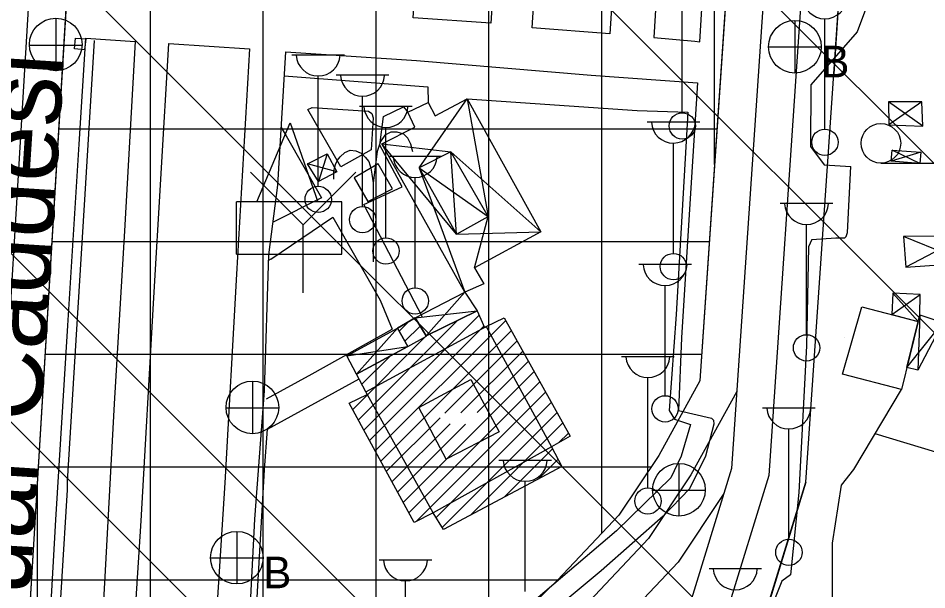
# Model space of a CAD drawing. Extents: x 417995 to 421451, y 4454518 to 4458015.
# Drawn here: x 420623.1 to 420743.9, y 4456059.6 to 4456135.7 of the extents above; entities that cross this region are included whole.
import ezdxf

# ---------------------------------------------------------------- set-up
doc = ezdxf.new("R2010")
doc.units = 0
for name, color, linetype in [('ADAKENARI', 7, 'Continuous'), ('B_Dini tesis', 7, 'Continuous'), ('B_Mesken', 7, 'Continuous'), ('B_Sundurma', 7, 'Continuous'), ('B_Tarama', 7, 'Continuous'), ('B_Teras', 7, 'Continuous'), ('Hid_Havuz', 7, 'Continuous'), ('KALDIRIM_FAT', 7, 'Continuous'), ('PL_SAY_SPOR', 7, 'Continuous'), ('PL_TİCARET', 7, 'Continuous'), ('S_Abide', 7, 'Continuous'), ('S_Cad_Sok_Lambasi', 7, 'Continuous'), ('S_Rogar_Kapagi', 7, 'Continuous'), ('S_Rogar_Kapagi_Buski', 7, 'Continuous'), ('S_Tek_Agac', 7, 'Continuous'), ('S_Yangin_Vanasi', 7, 'Continuous'), ('Sinir_Cit_bir_taraf', 7, 'Continuous'), ('Sinir_itirazli_Mulkiyet', 7, 'Continuous'), ('Sinir_Parmaklik_bir_taraf', 7, 'Continuous'), ('Sinir_Yesil_Cit', 7, 'Continuous'), ('SN_TR_SIVILASMA', 7, 'Continuous'), ('TRFAT_SPOR', 7, 'Continuous'), ('TRFAT_TİCARET', 7, 'Continuous'), ('Y_Cadde_Yol', 7, 'Continuous'), ('Yol_Kaldirim_kenari_bordurtasi', 7, 'Continuous'), ('Yol_Sose', 7, 'Continuous')]:
    doc.layers.add(name, color=color, linetype=linetype)

msp = doc.modelspace()

# ---------------------------------------------------------------- linework, layer by layer
at = {"layer": 'ADAKENARI'}
for p, q in [((420742.27, 4456506.47), (420713.73, 4456087.47)), ((420748.52, 4456377.44), (420731.55, 4456128.29)), ((420623.45, 4456037.14), (420640, 4456310.1)), ((420727.85, 4456073.98), (420731.55, 4456128.29)), ((420713.73, 4456087.47), (420708.28, 4456077.52)), ((420708.28, 4456077.52), (420702.99, 4456069.58)), ((420727.85, 4456073.98), (420714.2, 4456029.58)), ((420702.99, 4456069.58), (420694.8, 4456060.91)), ((420694.8, 4456060.91), (420687.13, 4456053.49))]:
    msp.add_line(p, q, dxfattribs=at)
at = {"layer": 'B_Dini tesis'}
for points in [[(420677.36, 4456093.42), (420684.13, 4456096.75), (420685.1, 4456094.55), (420685.31, 4456094.67), (420687.74, 4456095.84), (420696.52, 4456080.08), (420694.01, 4456078.66), (420695.37, 4456076.05), (420679.64, 4456067.68), (420678.29, 4456069.87), (420675.75, 4456068.6), (420667.1, 4456084.46), (420669.53, 4456085.64), (420669.35, 4456085.97), (420668.1, 4456088.36), (420674.92, 4456092.02), (420673.54, 4456094.45), (420675.88, 4456095.82)], [(420685.31, 4456094.67), (420694.01, 4456078.66), (420678.29, 4456069.87), (420669.35, 4456085.97)], [(420676.36, 4456083.9), (420683.29, 4456087.65), (420687.04, 4456080.67), (420680.03, 4456077.02)]]:
    msp.add_lwpolyline(points, close=True, dxfattribs=at)
at = {"layer": 'B_Mesken'}
msp.add_lwpolyline([(420735.26, 4456097.32), (420742.75, 4456095.37), (420740.57, 4456086.29), (420732.71, 4456088.36)], close=True, dxfattribs=at)
at = {"layer": 'B_Sundurma'}
for p, q in [((420676.44, 4456115.8), (420682.81, 4456125)), ((420682.81, 4456125), (420685.61, 4456109.31)), ((420743.37, 4456121.35), (420738.82, 4456124.6)), ((420743.28, 4456124.6), (420738.86, 4456121.5)), ((420681.38, 4456106.99), (420671.44, 4456119.01)), ((420671.44, 4456119.01), (420680.64, 4456117.93)), ((420664.17, 4456117.66), (420663.05, 4456113.97)), ((420680.64, 4456117.93), (420692.59, 4456107.3)), ((420681.38, 4456106.99), (420680.64, 4456117.93)), ((420743.12, 4456117.87), (420739.18, 4456116.67)), ((420743, 4456116.38), (420739.33, 4456118.15)), ((420665.46, 4456115.27), (420661.59, 4456116.31)), ((420676.44, 4456115.8), (420682.5, 4456099.25)), ((420676.44, 4456115.8), (420685.61, 4456109.31)), ((420683.79, 4456102.49), (420685.61, 4456109.31)), ((420681.38, 4456106.99), (420692.59, 4456107.3)), ((420749.31, 4456103.17), (420740.84, 4456106.65)), ((420749.05, 4456106.74), (420741.13, 4456102.58)), ((420682.5, 4456099.25), (420677.36, 4456093.42)), ((420739.27, 4456096.28), (420743.03, 4456098.96)), ((420742.75, 4456095.37), (420739.39, 4456099.13)), ((420675.88, 4456095.82), (420684.13, 4456096.75)), ((420743.01, 4456096.25), (420742.74, 4456088.87)), ((420741.27, 4456089.22), (420746.07, 4456095.23)), ((420668.1, 4456088.36), (420673.54, 4456094.45)), ((420666.8, 4456090.8), (420674.92, 4456092.02))]:
    msp.add_line(p, q, dxfattribs=at)
for points in [[(420630.71, 4456133.04), (420632.09, 4456132.95), (420631.93, 4456131.5), (420630.58, 4456131.61)], [(420682.5, 4456099.25), (420671.44, 4456119.01), (420675.84, 4456121.21), (420674.92, 4456123.22), (420677.63, 4456124.47), (420678.57, 4456122.72), (420682.81, 4456125), (420692.59, 4456107.3), (420683.79, 4456102.49), (420685.03, 4456100.34), (420682.5, 4456099.25)], [(420743.37, 4456121.35), (420743.28, 4456124.6), (420738.82, 4456124.6), (420738.86, 4456121.5)], [(420664.17, 4456117.66), (420665.46, 4456115.27), (420663.05, 4456113.97), (420661.59, 4456116.31)], [(420681.38, 4456106.99), (420685.61, 4456109.31), (420680.64, 4456117.93), (420676.44, 4456115.8)], [(420743.12, 4456117.87), (420743, 4456116.38), (420739.18, 4456116.67), (420739.33, 4456118.15)], [(420749.31, 4456103.17), (420749.05, 4456106.74), (420740.84, 4456106.65), (420741.13, 4456102.58)], [(420675.88, 4456095.82), (420682.5, 4456099.25), (420684.13, 4456096.75), (420677.36, 4456093.42)], [(420739.27, 4456096.28), (420742.75, 4456095.37), (420743.01, 4456096.25), (420743.03, 4456098.96), (420739.39, 4456099.13)], [(420741.27, 4456089.22), (420742.75, 4456095.37), (420743.01, 4456096.25), (420746.07, 4456095.23), (420742.74, 4456088.87)], [(420668.1, 4456088.36), (420666.8, 4456090.8), (420673.54, 4456094.45), (420674.92, 4456092.02)]]:
    msp.add_lwpolyline(points, close=True, dxfattribs=at)
at = {"layer": 'B_Tarama'}
for p, q in [((420669.06, 4456080.87), (420684.38, 4456096.19)), ((420668.31, 4456082.24), (420681.54, 4456095.47)), ((420669.81, 4456079.5), (420685.03, 4456094.72)), ((420670.56, 4456078.13), (420687.93, 4456095.5)), ((420673.76, 4456094.06), (420675.02, 4456095.32)), ((420674.53, 4456092.71), (420676.55, 4456094.73)), ((420667.56, 4456083.61), (420677.36, 4456093.42)), ((420671.31, 4456076.75), (420688.69, 4456094.13)), ((420679.85, 4456083.17), (420689.45, 4456092.77)), ((420681.98, 4456083.19), (420690.2, 4456091.41)), ((420668.81, 4456086.99), (420672.6, 4456090.78)), ((420684.14, 4456083.23), (420690.96, 4456090.05)), ((420674.3, 4456071.26), (420691.72, 4456088.68)), ((420675.05, 4456069.89), (420692.48, 4456087.32)), ((420676.02, 4456068.74), (420693.24, 4456085.96)), ((420678.67, 4456069.26), (420694, 4456084.6)), ((420672.05, 4456075.38), (420679.22, 4456082.55)), ((420679.47, 4456067.95), (420694.76, 4456083.23)), ((420672.8, 4456074.01), (420680.53, 4456081.73)), ((420673.55, 4456072.64), (420682.59, 4456081.68)), ((420683.24, 4456069.59), (420695.52, 4456081.87)), ((420694.97, 4456079.2), (420696.28, 4456080.51)), ((420687.77, 4456072.01), (420694.15, 4456078.39)), ((420692.31, 4456074.42), (420694.88, 4456076.99))]:
    msp.add_line(p, q, dxfattribs=at)
at = {"layer": 'B_Teras'}
msp.add_lwpolyline([(420673.54, 4456094.45), (420674.92, 4456092.02), (420677.38, 4456093.39), (420675.88, 4456095.82)], close=True, dxfattribs=at)
at = {"layer": 'Hid_Havuz'}
for points in [[(420675.56, 4456117.91), (420675.31, 4456118.96), (420674.93, 4456119.73), (420674.37, 4456120.29), (420673.49, 4456120.54), (420672.65, 4456120.54), (420671.85, 4456120.15), (420671.29, 4456119.31), (420670.83, 4456117.98), (420670.31, 4456113.78)], [(420665.06, 4456114.27), (420665.09, 4456115.29), (420665.3, 4456116.23), (420665.58, 4456116.83), (420665.9, 4456117.28), (420666.56, 4456117.84), (420667.26, 4456118.16), (420668, 4456118.05), (420668.7, 4456117.74), (420669.26, 4456117.21), (420669.71, 4456116.65), (420669.99, 4456115.74), (420670.13, 4456114.94), (420670.31, 4456113.78), (420670.31, 4456103.28)]]:
    msp.add_lwpolyline(points, dxfattribs=at)
msp.add_lwpolyline([(420667.8, 4456114.48), (420669.58, 4456111.3), (420672.89, 4456113.02), (420670.97, 4456116.33)], close=True, dxfattribs=at)
at = {"layer": 'KALDIRIM_FAT'}
for p, q in [((420747.16, 4456504.72), (420717.95, 4456075.79)), ((420752.15, 4456504.38), (420722.9, 4456074.87)), ((420618.56, 4456039.04), (420635.14, 4456312.53)), ((420718.64, 4456086.03), (420712.56, 4456074.93)), ((420717.95, 4456075.79), (420701.55, 4456022.47)), ((420722.9, 4456074.87), (420706.68, 4456022.13)), ((420712.56, 4456074.93), (420706.92, 4456066.45)), ((420716.84, 4456072.34), (420710.84, 4456063.33)), ((420716.94, 4456072.51), (420716.84, 4456072.34)), ((420706.92, 4456066.45), (420698.36, 4456057.39)), ((420710.84, 4456063.33), (420701.91, 4456053.88))]:
    msp.add_line(p, q, dxfattribs=at)
at = {"layer": 'PL_SAY_SPOR'}
msp.add_lwpolyline([(420858.4, 4456215.86), (420846.76, 4456021.02), (420843.59, 4456018.22), (420716.31, 4456026.52), (420714.2, 4456029.58), (420727.85, 4456073.98), (420731.55, 4456128.29), (420748.52, 4456377.44), (420853.02, 4456372.3), (420866.39, 4456349.6)], close=True, dxfattribs=at)
at = {"layer": 'PL_TİCARET'}
msp.add_lwpolyline([(420742.27, 4456506.47), (420713.73, 4456087.47), (420708.28, 4456077.52), (420702.99, 4456069.58), (420694.8, 4456060.91), (420687.13, 4456053.49), (420677.56, 4456046.59), (420663.97, 4456038.32), (420651.15, 4456031.6), (420647.64, 4456030.99), (420629.4, 4456032.18), (420626.42, 4456033.36), (420623.45, 4456037.14), (420640, 4456310.1)], dxfattribs=at)
at = {"layer": 'S_Abide'}
for p, q in [((420654.84, 4456111.29), (420659.29, 4456121.79)), ((420659.29, 4456121.79), (420662.96, 4456111.29)), ((420652.15, 4456104.29), (420652.15, 4456111.29)), ((420666.15, 4456111.29), (420652.15, 4456111.29)), ((420666.15, 4456104.29), (420666.15, 4456111.29)), ((420666.15, 4456104.29), (420666.15, 4456111.05)), ((420652.15, 4456104.29), (420666.15, 4456104.29))]:
    msp.add_line(p, q, dxfattribs=at)
at = {"layer": 'S_Cad_Sok_Lambasi'}
for p, q in [((420711.41, 4456123.12), (420711.41, 4456137.8)), ((420730.37, 4456120.95), (420730.37, 4456135.63)), ((420659.5, 4456130.85), (420666.5, 4456130.85)), ((420663, 4456113.35), (420663, 4456128.02)), ((420665.4, 4456128.15), (420672.4, 4456128.15)), ((420668.9, 4456110.65), (420668.9, 4456125.32)), ((420668.51, 4456123.99), (420675.51, 4456123.99)), ((420672.01, 4456106.49), (420672.01, 4456121.16)), ((420706.72, 4456121.91), (420713.72, 4456121.91)), ((420710.22, 4456104.41), (420710.22, 4456119.09)), ((420672.4, 4456117.34), (420679.4, 4456117.34)), ((420675.9, 4456099.84), (420675.9, 4456114.51)), ((420724.43, 4456111.09), (420731.43, 4456111.09)), ((420727.93, 4456093.59), (420727.93, 4456108.27)), ((420705.62, 4456102.97), (420712.62, 4456102.97)), ((420709.12, 4456085.47), (420709.12, 4456100.14)), ((420703.34, 4456090.71), (420710.34, 4456090.71)), ((420706.84, 4456073.21), (420706.84, 4456087.88)), ((420722.08, 4456083.88), (420729.08, 4456083.88)), ((420725.58, 4456066.38), (420725.58, 4456081.05)), ((420687.02, 4456076.9), (420694.02, 4456076.9)), ((420690.52, 4456059.4), (420690.52, 4456074.08)), ((420671.09, 4456063.65), (420678.09, 4456063.65)), ((420714.96, 4456062.46), (420721.96, 4456062.46)), ((420674.59, 4456046.15), (420674.59, 4456060.82))]:
    msp.add_line(p, q, dxfattribs=at)
for centre in [(420711.41, 4456121.37), (420730.37, 4456119.2), (420663, 4456111.6), (420668.9, 4456108.9), (420672.01, 4456104.74), (420710.22, 4456102.66), (420675.9, 4456098.09), (420727.93, 4456091.84), (420709.12, 4456083.72), (420706.84, 4456071.46), (420725.58, 4456064.63)]:
    msp.add_circle(centre, 1.75, dxfattribs=at)
for centre in [(420730.37, 4456138.56), (420663, 4456130.95), (420668.9, 4456128.25), (420672.01, 4456124.09), (420710.22, 4456122.02), (420675.9, 4456117.44), (420727.93, 4456111.19), (420709.12, 4456103.07), (420706.84, 4456090.81), (420725.58, 4456083.98), (420690.52, 4456077.01), (420674.59, 4456063.75), (420718.46, 4456062.57)]:
    msp.add_arc(centre, 2.93, 183.298, 356.9072, dxfattribs=at)
at = {"layer": 'S_Rogar_Kapagi'}
for p, q in [((420628.15, 4456128.68), (420628.15, 4456135.68)), ((420624.58, 4456132.14), (420631.58, 4456132.14)), ((420654.3, 4456080.39), (420654.3, 4456087.39)), ((420650.73, 4456083.86), (420657.73, 4456083.86)), ((420711.01, 4456069.43), (420711.01, 4456076.43)), ((420707.44, 4456072.89), (420714.44, 4456072.89))]:
    msp.add_line(p, q, dxfattribs=at)
for centre in [(420628.1, 4456132.21), (420654.25, 4456083.92), (420710.96, 4456072.96)]:
    msp.add_circle(centre, 3.5, dxfattribs=at)
at = {"layer": 'S_Rogar_Kapagi_Buski'}
for p, q in [((420726.38, 4456135.41), (420726.38, 4456128.41)), ((420722.88, 4456131.91), (420729.88, 4456131.91)), ((420652.18, 4456067.42), (420652.18, 4456060.42)), ((420648.68, 4456063.92), (420655.68, 4456063.92))]:
    msp.add_line(p, q, dxfattribs=at)
for centre in [(420726.38, 4456131.91), (420652.18, 4456063.92)]:
    msp.add_circle(centre, 3.5, dxfattribs=at)
at = {"layer": 'S_Tek_Agac'}
msp.add_line((420737.82, 4456116.43), (420744.82, 4456116.43), dxfattribs=at)
msp.add_circle((420737.82, 4456119.06), 2.63, dxfattribs=at)
at = {"layer": 'S_Yangin_Vanasi'}
for p, q in [((420660.98, 4456108.22), (420653.98, 4456115.22)), ((420660.98, 4456108.22), (420668.01, 4456115.22)), ((420660.98, 4456099.16), (420660.98, 4456108.22))]:
    msp.add_line(p, q, dxfattribs=at)
at = {"layer": 'Sinir_Cit_bir_taraf'}
for points in [[(420732.57, 4456073.56), (420734.2, 4456075.64), (420740.57, 4456086.29)], [(420729.4, 4456033.55), (420730.14, 4456036.39), (420731.4, 4456052.42), (420731.39, 4456065.86), (420732.57, 4456073.56)]]:
    msp.add_lwpolyline(points, dxfattribs=at)
at = {"layer": 'Sinir_itirazli_Mulkiyet'}
msp.add_lwpolyline([(420783.51, 4456067.02), (420774.06, 4456070.08), (420745.11, 4456077.97), (420737.04, 4456080.39)], dxfattribs=at)
at = {"layer": 'Sinir_Parmaklik_bir_taraf'}
msp.add_lwpolyline([(420633.19, 4456132.75), (420631.96, 4456112.28), (420630.53, 4456089.25), (420629.61, 4456074.04), (420629.6, 4456072.95), (420628.12, 4456048.47), (420627.59, 4456039.75)], dxfattribs=at)
at = {"layer": 'Sinir_Yesil_Cit'}
for points in [[(420682.81, 4456125), (420705.39, 4456123.43), (420712.13, 4456123.21)], [(420712.13, 4456123.21), (420710.61, 4456096.28), (420709.66, 4456083.51), (420710.39, 4456082.33), (420712.48, 4456081.66), (420711.25, 4456077.44), (420709.88, 4456074.53), (420702.64, 4456067.48), (420682.72, 4456050.5), (420668.55, 4456037.71), (420662.7, 4456032.94), (420657.34, 4456030.13), (420653.36, 4456029.27), (420653.72, 4456038.55), (420655.86, 4456075.62), (420656.27, 4456081.02), (420668.43, 4456087.74)], [(420656.12, 4456085.07), (420662.19, 4456088.4), (420672.84, 4456094.34)]]:
    msp.add_lwpolyline(points, dxfattribs=at)
at = {"layer": 'SN_TR_SIVILASMA'}
for p, q in [((421272.55, 4455588.71), (420264.03, 4456597.24)), ((421272.32, 4455566.5), (420257.91, 4456580.91)), ((421271.63, 4455499.84), (420239.54, 4456531.93)), ((421271.16, 4455455.4), (420227.3, 4456499.27)), ((421270.93, 4455433.18), (420221.05, 4456483.06))]:
    msp.add_line(p, q, dxfattribs=at)
at = {"layer": 'TRFAT_SPOR'}
for p, q in [((420732.95, 4456130.72), (420732.95, 4456130.72)), ((420732.95, 4456111.97), (420732.95, 4456111.97)), ((420732.95, 4456093.22), (420732.95, 4456093.22)), ((420732.95, 4456074.47), (420732.95, 4456074.47))]:
    msp.add_line(p, q, dxfattribs=at)
at = {"layer": 'TRFAT_TİCARET'}
for p, q in [((420640.69, 4456031.44), (420640.69, 4456593)), ((420655.69, 4456033.98), (420655.69, 4456580.72)), ((420700.69, 4456067.15), (420700.69, 4456543.85)), ((420715.69, 4456116.24), (420715.69, 4456531.57)), ((420670.69, 4456042.41), (420670.69, 4456309.64)), ((420685.69, 4456052.45), (420685.69, 4456309.64)), ((420628.53, 4456120.99), (420716.01, 4456120.99)), ((420627.62, 4456105.99), (420714.99, 4456105.99)), ((420626.72, 4456090.99), (420713.97, 4456090.99)), ((420625.81, 4456075.99), (420707.26, 4456075.99)), ((420625.69, 4456034.29), (420625.69, 4456074.08)), ((420624.9, 4456060.99), (420694.88, 4456060.99))]:
    msp.add_line(p, q, dxfattribs=at)
at = {"layer": 'Yol_Kaldirim_kenari_bordurtasi'}
for points in [[(420658.49, 4456128.02), (420677.56, 4456126.57), (420677.63, 4456124.47)], [(420666, 4456115.94), (420661.6, 4456123.57), (420662.18, 4456123.84), (420669.69, 4456123.32), (420670.15, 4456123.03), (420670.29, 4456122.44), (420670.03, 4456118.18), (420666, 4456115.94)], [(420676.85, 4456095.93), (420669.07, 4456110.92), (420674.15, 4456113.28), (420671.19, 4456118.8), (420671.7, 4456122.64), (420674.33, 4456123.9), (420674.92, 4456123.22)], [(420658.08, 4456121.18), (420658.76, 4456120.07), (420663.43, 4456111.81), (420656.99, 4456108.58)], [(420656.72, 4456103.65), (420664.96, 4456109.24), (420671.22, 4456098.18), (420672.84, 4456094.34)], [(420656.72, 4456103.65), (420656.41, 4456103.46)]]:
    msp.add_lwpolyline(points, dxfattribs=at)
at = {"layer": 'Yol_Sose'}
for points in [[(420739.88, 4456293.42), (420742.03, 4456290.05), (420743.84, 4456286.82), (420745.4, 4456285.19), (420751.19, 4456284.32), (420753.96, 4456282.84), (420754.46, 4456281.25), (420754.36, 4456263.79), (420753.49, 4456240.81), (420752.09, 4456211.91), (420750.59, 4456188.83), (420747.12, 4456156.46), (420743.84, 4456137.51), (420735.92, 4456137.21), (420734.68, 4456133.91)], [(420675.61, 4456135.77), (420683.19, 4456251.24), (420686.42, 4456251.07), (420686.51, 4456253.39), (420690.2, 4456253.13), (420690.1, 4456250.9), (420693.34, 4456250.83), (420685.94, 4456135.04), (420675.61, 4456135.77)], [(420691.43, 4456134.42), (420698.93, 4456250.28), (420701.65, 4456250.09), (420701.93, 4456252.53), (420706.23, 4456252.21), (420706.15, 4456249.63), (420709.2, 4456249.54), (420701.79, 4456133.61), (420691.43, 4456134.42)], [(420721.51, 4456251.12), (420714.8, 4456251.47), (420707.63, 4456133.16), (420713.06, 4456132.65)], [(420713.06, 4456132.65), (420713.73, 4456132.56), (420716.61, 4456180.23), (420719.51, 4456227.27), (420721.51, 4456251.12)], [(420713.06, 4456132.65), (420713.73, 4456132.56), (420716.61, 4456180.23), (420719.51, 4456227.27), (420721.51, 4456251.12)], [(420734.68, 4456133.91), (420728.51, 4456126.85), (420728.44, 4456118.62), (420730.28, 4456116.2), (420733.83, 4456115.97)], [(420638.65, 4456132.61), (420637.23, 4456107.41), (420635.87, 4456084.4), (420634.58, 4456060.58), (420633.45, 4456040.22), (420632.49, 4456039.5), (420626.49, 4456039.81), (420628.12, 4456068.96), (420629.69, 4456094.81), (420631.22, 4456118.93), (420632.11, 4456133.07)], [(420632.11, 4456133.07), (420638.65, 4456132.61)], [(420637.66, 4456040.44), (420639.46, 4456068.81), (420641.11, 4456097.76), (420643.14, 4456132.35), (420653.86, 4456131.63), (420652.12, 4456101.65), (420650.57, 4456073.88), (420648.67, 4456044.03), (420648.42, 4456039.67), (420648.07, 4456039.42)], [(420647.89, 4456027.27), (420628.43, 4456029.03), (420624.11, 4456031.59), (420622.11, 4456034.75), (420621.28, 4456038.54), (420632.96, 4456037.35), (420639.94, 4456036.26), (420652.81, 4456035.95), (420652.9, 4456036.19), (420654.59, 4456069.03), (420655.86, 4456086.14), (420656.43, 4456104.21), (420657.62, 4456113.47), (420658.5, 4456128.25), (420658.71, 4456131.25), (420676.08, 4456130.08), (420699.31, 4456128.14)], [(420699.31, 4456128.14), (420713.42, 4456127.12), (420712.62, 4456114.55), (420711.32, 4456093.17), (420710.89, 4456083.49), (420715.29, 4456082.49), (420715.57, 4456082.23), (420715.59, 4456081.69), (420714.51, 4456077.43), (420712.38, 4456073.06), (420708.87, 4456069.43), (420700.62, 4456062.15), (420683.4, 4456047.8), (420664.07, 4456031.39), (420657.85, 4456027.3), (420656.32, 4456026.89), (420647.89, 4456027.27)], [(420728.63, 4456106.28), (420731.81, 4456106.48), (420733, 4456106.5), (420733.18, 4456106.65), (420733.38, 4456107.18), (420733.83, 4456115.97)], [(420728.63, 4456106.28), (420728.18, 4456105.29), (420727.94, 4456092.13), (420726.91, 4456072.6), (420725.8, 4456061.64), (420724.65, 4456060.81), (420717.99, 4456044.23), (420713.35, 4456030.93), (420707.14, 4456016.51), (420705.51, 4456007.8), (420705.43, 4456000.94)]]:
    msp.add_lwpolyline(points, dxfattribs=at)

# ---------------------------------------------------------------- texts
at = {"layer": 'S_Rogar_Kapagi_Buski'}
for p in [(420729.88, 4456127.84), (420655.68, 4456059.85)]:
    msp.add_text('B', height=4.2, dxfattribs=at).set_placement(p)
at = {"layer": 'Y_Cadde_Yol'}
msp.add_text('Fuar Caddesi', height=10, rotation=86.3255, dxfattribs=at).set_placement((420624.09, 4456050.67))

doc.saveas('drawing.dxf')
